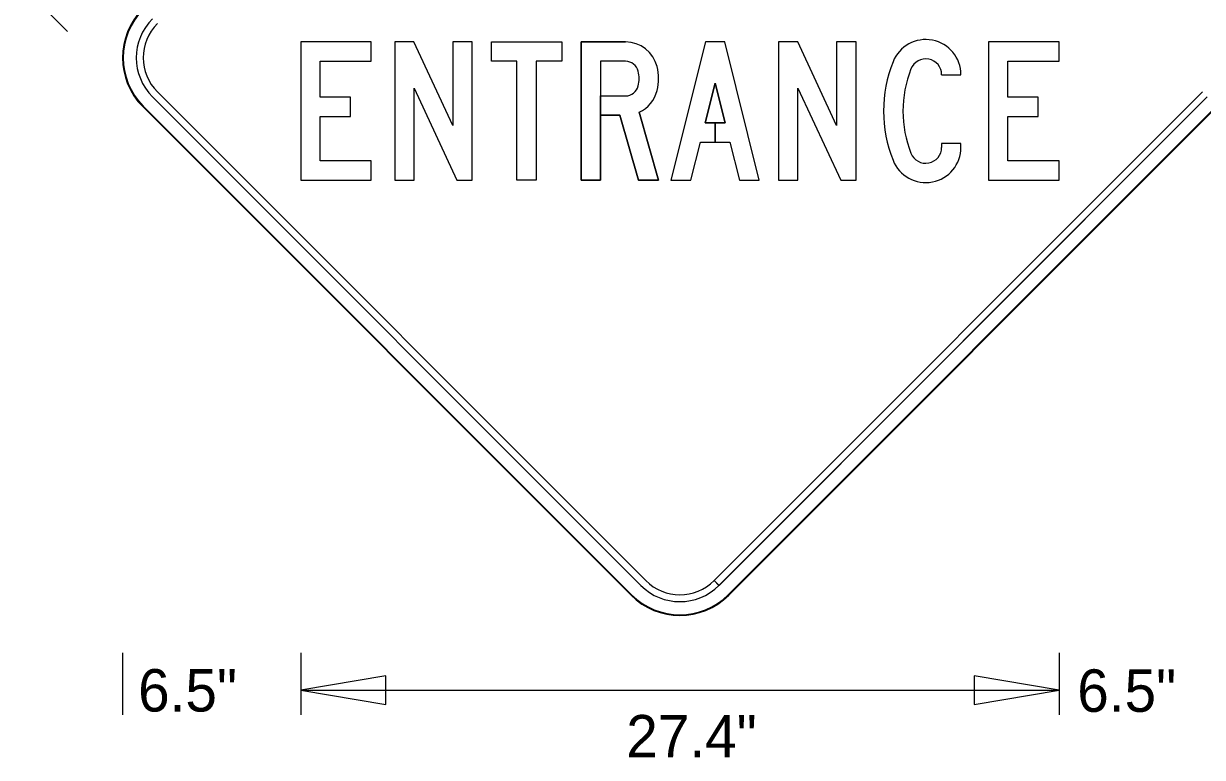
# Model space of a CAD drawing. Extents: x 0 to 770, y 0 to 495.
# Drawn here: x 32.7 to 130, y 204 to 264.5 of the extents above; entities that cross this region are included whole.
import ezdxf

# ---------------------------------------------------------------- set-up
doc = ezdxf.new("R2010")
doc.units = 0
for name, color, linetype in [('Dimension', 7, 'Continuous'), ('GSBWFill', 7, 'Continuous'), ('GSColorFill', 7, 'Continuous'), ('GSDims', 7, 'Continuous'), ('GSOutline', 7, 'Continuous'), ('TextStructures', 7, 'Continuous')]:
    doc.layers.add(name, color=color, linetype=linetype)

msp = doc.modelspace()

# ---------------------------------------------------------------- linework, layer by layer
at = {"layer": 'Dimension'}
for points in [[(55.619, 209.542), (62.635, 208.353), (62.635, 210.73)], [(118.206, 209.542), (111.189, 210.73), (111.189, 208.353)]]:
    msp.add_lwpolyline(points, close=True, dxfattribs=at)
at = {"layer": 'GSBWFill'}
for p, q in [((108.516, 260.301), (110.112, 260.301)), ((84.091, 218.576), (43.785, 258.882)), ((130.039, 258.882), (89.738, 218.58)), ((43.382, 258.479), (83.688, 218.173)), ((82.425, 258.562), (82.425, 258.562)), ((90.141, 218.177), (130.442, 258.479)), ((42.576, 257.673), (82.882, 217.367)), ((90.943, 217.367), (131.249, 257.673)), ((90.137, 218.173), (89.734, 218.576)), ((89.738, 218.58), (90.141, 218.177))]:
    msp.add_line(p, q, dxfattribs=at)
for points in [[(57.215, 253.204), (57.215, 256.852), (59.712, 256.852), (59.712, 258.448), (57.215, 258.448), (57.215, 261.412), (61.433, 261.412), (61.433, 263.008), (55.619, 263.008), (55.619, 251.608), (61.433, 251.608), (61.433, 253.204)], [(68.501, 251.608), (69.755, 251.608), (69.755, 263.008), (68.159, 263.008), (68.159, 256.119), (64.948, 263.008), (63.371, 263.008), (63.371, 251.608), (64.967, 251.608), (64.967, 259.189)], [(73.46, 261.412), (71.351, 261.412), (71.351, 263.008), (77.165, 263.008), (77.165, 261.412), (75.056, 261.412), (75.056, 251.608), (73.46, 251.608)], [(89.819, 256.339), (88.999, 256.339), (89.819, 259.62), (90.639, 256.339), (89.82, 256.339), (89.82, 254.743), (91.038, 254.743), (91.822, 251.608), (93.467, 251.608), (90.617, 263.008), (89.021, 263.008), (86.171, 251.608), (87.816, 251.608), (88.6, 254.743), (89.819, 254.743)], [(100.193, 251.608), (101.447, 251.608), (101.447, 263.008), (99.851, 263.008), (99.851, 256.119), (96.64, 263.008), (95.063, 263.008), (95.063, 251.608), (96.659, 251.608), (96.659, 259.189)], [(113.988, 253.204), (113.988, 256.852), (116.485, 256.852), (116.485, 258.448), (113.988, 258.448), (113.988, 261.412), (118.206, 261.412), (118.206, 263.008), (112.392, 263.008), (112.392, 251.608), (118.206, 251.608), (118.206, 253.204)]]:
    msp.add_lwpolyline(points, close=True, dxfattribs=at)
for points in [[(82.425, 261.412), (80.357, 261.412), (80.357, 251.608), (78.761, 251.608), (78.761, 263.008), (82.425, 263.008)], [(83.549, 257.214), (85.145, 251.608), (83.486, 251.608), (81.96, 256.966), (80.358, 256.966), (80.358, 258.562), (82.425, 258.562)], [(110.112, 254.316), (110.112, 254.629), (108.516, 254.629), (108.516, 254.316)]]:
    msp.add_lwpolyline(points, dxfattribs=at)
for centre, radius, start, end in [((46.607, 261.703), 5.7, 135, 225), ((46.607, 261.703), 4.56, 135, 225), ((46.607, 261.703), 3.99, 135, 225), ((86.912, 221.398), 4.56, 225, 315), ((86.912, 221.398), 3.99, 225, 315), ((86.912, 221.398), 5.7, 225, 315)]:
    msp.add_arc(centre, radius, start, end, dxfattribs=at)
for centre, major_axis, start_param, end_param in [((82.425, 260.329), (0, 2.679), 4.954755, 6.283185), ((107.205, 260.301), (0, 2.907), 4.712389, 7.477539), ((82.425, 260.329), (0, 1.083), 4.954755, 6.283185), ((81.041, 259.987), (0, 4.104), 4.470023, 4.954755), ((114.775, 257.308), (0, 11.047), 1.194353, 1.947239), ((114.775, 257.308), (0, 9.451), 1.194353, 1.947239), ((107.205, 260.301), (0, 1.311), 4.712389, 7.477539), ((81.041, 259.987), (0, 2.508), 4.470023, 4.954755), ((82.425, 259.645), (0, 1.083), 3.141593, 4.470023), ((82.425, 259.645), (0, 2.679), 3.574819, 4.470023), ((107.205, 254.316), (0, 2.907), 1.947239, 4.712389), ((107.205, 254.316), (0, 1.311), 1.947239, 4.712389)]:
    msp.add_ellipse(centre, major_axis=major_axis, ratio=0.999991, start_param=start_param, end_param=end_param, dxfattribs=at)
at = {"layer": 'GSColorFill'}
for p, q in [((108.516, 260.301), (110.112, 260.301)), ((84.091, 218.576), (43.785, 258.882)), ((130.039, 258.882), (89.738, 218.58)), ((43.382, 258.479), (83.688, 218.173)), ((82.425, 258.562), (82.425, 258.562)), ((90.141, 218.177), (130.442, 258.479)), ((42.576, 257.673), (82.882, 217.367)), ((42.576, 257.673), (82.882, 217.367)), ((82.922, 217.407), (42.616, 257.713)), ((131.208, 257.713), (90.903, 217.408)), ((90.943, 217.367), (131.249, 257.673)), ((90.943, 217.368), (131.249, 257.673)), ((90.137, 218.173), (89.734, 218.576)), ((89.738, 218.58), (90.141, 218.177)), ((90.903, 217.408), (90.943, 217.368)), ((90.943, 217.367), (90.903, 217.407))]:
    msp.add_line(p, q, dxfattribs=at)
for points in [[(57.215, 253.204), (57.215, 256.852), (59.712, 256.852), (59.712, 258.448), (57.215, 258.448), (57.215, 261.412), (61.433, 261.412), (61.433, 263.008), (55.619, 263.008), (55.619, 251.608), (61.433, 251.608), (61.433, 253.204)], [(68.501, 251.608), (69.755, 251.608), (69.755, 263.008), (68.159, 263.008), (68.159, 256.119), (64.948, 263.008), (63.371, 263.008), (63.371, 251.608), (64.967, 251.608), (64.967, 259.189)], [(73.46, 261.412), (71.351, 261.412), (71.351, 263.008), (77.165, 263.008), (77.165, 261.412), (75.056, 261.412), (75.056, 251.608), (73.46, 251.608)], [(89.819, 256.339), (88.999, 256.339), (89.819, 259.62), (90.639, 256.339), (89.82, 256.339), (89.82, 254.743), (91.038, 254.743), (91.822, 251.608), (93.467, 251.608), (90.617, 263.008), (89.021, 263.008), (86.171, 251.608), (87.816, 251.608), (88.6, 254.743), (89.819, 254.743)], [(100.193, 251.608), (101.447, 251.608), (101.447, 263.008), (99.851, 263.008), (99.851, 256.119), (96.64, 263.008), (95.063, 263.008), (95.063, 251.608), (96.659, 251.608), (96.659, 259.189)], [(113.988, 253.204), (113.988, 256.852), (116.485, 256.852), (116.485, 258.448), (113.988, 258.448), (113.988, 261.412), (118.206, 261.412), (118.206, 263.008), (112.392, 263.008), (112.392, 251.608), (118.206, 251.608), (118.206, 253.204)]]:
    msp.add_lwpolyline(points, close=True, dxfattribs=at)
for points in [[(82.425, 261.412), (80.357, 261.412), (80.357, 251.608), (78.761, 251.608), (78.761, 263.008), (82.425, 263.008)], [(83.549, 257.214), (85.145, 251.608), (83.486, 251.608), (81.96, 256.966), (80.358, 256.966), (80.358, 258.562), (82.425, 258.562)], [(110.112, 254.316), (110.112, 254.629), (108.516, 254.629), (108.516, 254.316)]]:
    msp.add_lwpolyline(points, dxfattribs=at)
for centre, radius, start, end in [((46.607, 261.703), 5.7, 135, 225), ((46.607, 261.703), 5.7, 135, 225), ((46.607, 261.703), 5.643, 135, 225), ((46.607, 261.703), 4.56, 135, 225), ((46.607, 261.703), 3.99, 135, 225), ((86.912, 221.398), 4.56, 225, 315), ((86.912, 221.398), 3.99, 225, 315), ((86.912, 221.398), 5.7, 225, 315), ((86.912, 221.398), 5.7, 225, 315), ((86.912, 221.398), 5.643, 225, 315)]:
    msp.add_arc(centre, radius, start, end, dxfattribs=at)
for centre, major_axis, start_param, end_param in [((82.425, 260.329), (0, 2.679), 4.954755, 6.283185), ((107.205, 260.301), (0, 2.907), 4.712389, 7.477539), ((82.425, 260.329), (0, 1.083), 4.954755, 6.283185), ((81.041, 259.987), (0, 4.104), 4.470023, 4.954755), ((114.775, 257.308), (0, 11.047), 1.194353, 1.947239), ((114.775, 257.308), (0, 9.451), 1.194353, 1.947239), ((107.205, 260.301), (0, 1.311), 4.712389, 7.477539), ((81.041, 259.987), (0, 2.508), 4.470023, 4.954755), ((82.425, 259.645), (0, 1.083), 3.141593, 4.470023), ((82.425, 259.645), (0, 2.679), 3.574819, 4.470023), ((107.205, 254.316), (0, 2.907), 1.947239, 4.712389), ((107.205, 254.316), (0, 1.311), 1.947239, 4.712389)]:
    msp.add_ellipse(centre, major_axis=major_axis, ratio=0.999991, start_param=start_param, end_param=end_param, dxfattribs=at)
at = {"layer": 'GSDims'}
for p, q in [((36.369, 263.88), (32.741, 267.507)), ((40.906, 212.62), (40.906, 207.49)), ((55.619, 212.62), (55.619, 207.49)), ((55.619, 212.62), (55.619, 207.49)), ((118.206, 212.62), (118.206, 207.49)), ((118.206, 212.62), (118.206, 207.49)), ((55.619, 209.542), (118.206, 209.542))]:
    msp.add_line(p, q, dxfattribs=at)
at = {"layer": 'GSOutline'}
for p, q in [((82.425, 263.008), (78.761, 263.008)), ((82.425, 261.412), (82.425, 261.412)), ((108.516, 260.301), (110.112, 260.301)), ((43.785, 258.882), (84.091, 218.576)), ((89.734, 218.576), (130.039, 258.882)), ((43.382, 258.479), (83.688, 218.173)), ((90.137, 218.173), (130.442, 258.479)), ((42.576, 257.673), (82.882, 217.367)), ((90.943, 217.367), (131.249, 257.673))]:
    msp.add_line(p, q, dxfattribs=at)
for points in [[(57.215, 253.204), (57.215, 256.852), (59.712, 256.852), (59.712, 258.448), (57.215, 258.448), (57.215, 261.412), (61.433, 261.412), (61.433, 263.008), (55.619, 263.008), (55.619, 251.608), (61.433, 251.608), (61.433, 253.204)], [(68.501, 251.608), (69.755, 251.608), (69.755, 263.008), (68.159, 263.008), (68.159, 256.119), (64.948, 263.008), (63.371, 263.008), (63.371, 251.608), (64.967, 251.608), (64.967, 259.189)], [(73.46, 261.412), (71.351, 261.412), (71.351, 263.008), (77.165, 263.008), (77.165, 261.412), (75.056, 261.412), (75.056, 251.608), (73.46, 251.608)], [(88.6, 254.743), (91.038, 254.743), (91.822, 251.608), (93.467, 251.608), (90.617, 263.008), (89.021, 263.008), (86.171, 251.608), (87.816, 251.608)], [(100.193, 251.608), (101.447, 251.608), (101.447, 263.008), (99.851, 263.008), (99.851, 256.119), (96.64, 263.008), (95.063, 263.008), (95.063, 251.608), (96.659, 251.608), (96.659, 259.189)], [(113.988, 253.204), (113.988, 256.852), (116.485, 256.852), (116.485, 258.448), (113.988, 258.448), (113.988, 261.412), (118.206, 261.412), (118.206, 263.008), (112.392, 263.008), (112.392, 251.608), (118.206, 251.608), (118.206, 253.204)], [(90.639, 256.339), (89.819, 259.62), (88.999, 256.339)]]:
    msp.add_lwpolyline(points, close=True, dxfattribs=at)
for points in [[(78.761, 263.008), (78.761, 251.608), (80.357, 251.608), (80.357, 256.966), (81.96, 256.966), (83.486, 251.608), (85.145, 251.608), (83.549, 257.214)], [(82.425, 261.412), (80.357, 261.412), (80.357, 258.562), (82.425, 258.562)], [(110.112, 254.316), (110.112, 254.629), (108.516, 254.629), (108.516, 254.316)]]:
    msp.add_lwpolyline(points, dxfattribs=at)
for centre, radius, start, end in [((46.607, 261.703), 5.7, 135, 225), ((46.607, 261.703), 4.56, 135, 225), ((46.607, 261.703), 3.99, 135, 225), ((86.912, 221.398), 4.56, 225, 315), ((86.912, 221.398), 3.99, 225, 315), ((86.912, 221.398), 5.7, 225, 315)]:
    msp.add_arc(centre, radius, start, end, dxfattribs=at)
for centre, major_axis, start_param, end_param in [((82.425, 260.329), (0, 2.679), 4.954755, 6.283185), ((107.205, 260.301), (0, 2.907), 4.712389, 7.477539), ((82.425, 260.329), (0, 1.083), 4.954755, 6.283185), ((81.041, 259.987), (0, 4.104), 4.470023, 4.954755), ((114.775, 257.308), (0, 11.047), 1.194353, 1.947239), ((114.775, 257.308), (0, 9.451), 1.194353, 1.947239), ((107.205, 260.301), (0, 1.311), 4.712389, 7.477539), ((81.041, 259.987), (0, 2.508), 4.470023, 4.954755), ((82.425, 259.645), (0, 1.083), 3.141593, 4.470023), ((82.425, 259.645), (0, 2.679), 3.574819, 4.470023), ((107.205, 254.316), (0, 2.907), 1.947239, 4.712389), ((107.205, 254.316), (0, 1.311), 1.947239, 4.712389)]:
    msp.add_ellipse(centre, major_axis=major_axis, ratio=0.999991, start_param=start_param, end_param=end_param, dxfattribs=at)

# ---------------------------------------------------------------- texts
at = {"layer": 'TextStructures'}
for s, p in [('6.5"', (42.195, 207.773)), ('6.5"', (119.709, 207.75)), ('27.4"', (82.487, 203.99))]:
    msp.add_text(s, height=3.5, dxfattribs=at).set_placement(p)

doc.saveas('drawing.dxf')
